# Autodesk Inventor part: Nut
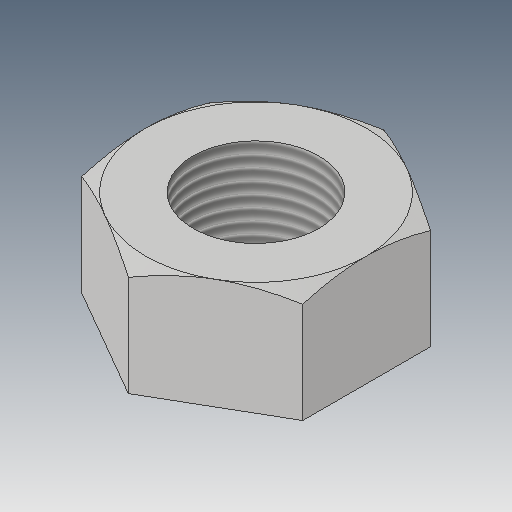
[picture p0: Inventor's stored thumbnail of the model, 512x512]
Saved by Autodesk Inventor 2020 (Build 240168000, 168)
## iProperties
Created: 2016-05
Part Number: Nut
Material: Generic
Document SubType Name: Modeling
Designer: CADCIM
Density: 1 g/cm^3
Appearance: Default
Author: CADCIM
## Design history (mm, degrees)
sketch "Sketch1"
  geometry: L1 (0, -33.255)-(-28.8, -16.628); L2 (-28.8, -16.628)-(-28.8, 16.628); L3 (-28.8, 16.628)-(0, 33.255); L4 (0, 33.255)-(28.8, 16.628); L5 (28.8, 16.628)-(28.8, -16.628); L6 (28.8, -16.628)-(0, -33.255); 2 further points
  constraints: 12 end point, 1 coincident, 13 other
  dimensions: "d0" = 57.6 distance between parallel lines of L2 L5
extrude "Extrusion1" new body sketch "Sketch1" stored distance "d1" = 28.8; taper "d2" = 0 deg
sketch "Sketch2"
  geometry: L1 (0, 33.255)-(-28.8, 16.628) reference; C1 r 28.8 at (0, 0); 1 further point
  constraints: 1 centre point, 1 coincident, 1 tangent
extrude "Extrusion2" sketch "Sketch2" distance "d3" = 28.8; taper "d4" = 60 deg
sketch "Sketch3"
  geometry: 1 further point
hole "Hole1" diameter "d7" = 32.752; stored, may be unused: countersink angle "d11" = 90 deg, drill point angle "d13" = 118 deg; dims "d5" = 10, "d6" = 10, "d8" = 72, "d9" = 4, "d10" = 2, "d12" = 85.1
body "Solid1"
